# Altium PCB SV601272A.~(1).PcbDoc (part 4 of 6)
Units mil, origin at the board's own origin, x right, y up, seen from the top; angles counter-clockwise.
Board outline 8300 x 9520 mil, 8 copper layers (Top Layer, Signal Layer 1, Signal Layer 2, Signal Layer 3, Signal Layer 4, Signal Layer 5, Signal Layer 6, Bottom Layer), stack 59.2 mil thick; 551 components, 303 nets, 1611 pads, 1923 vias.
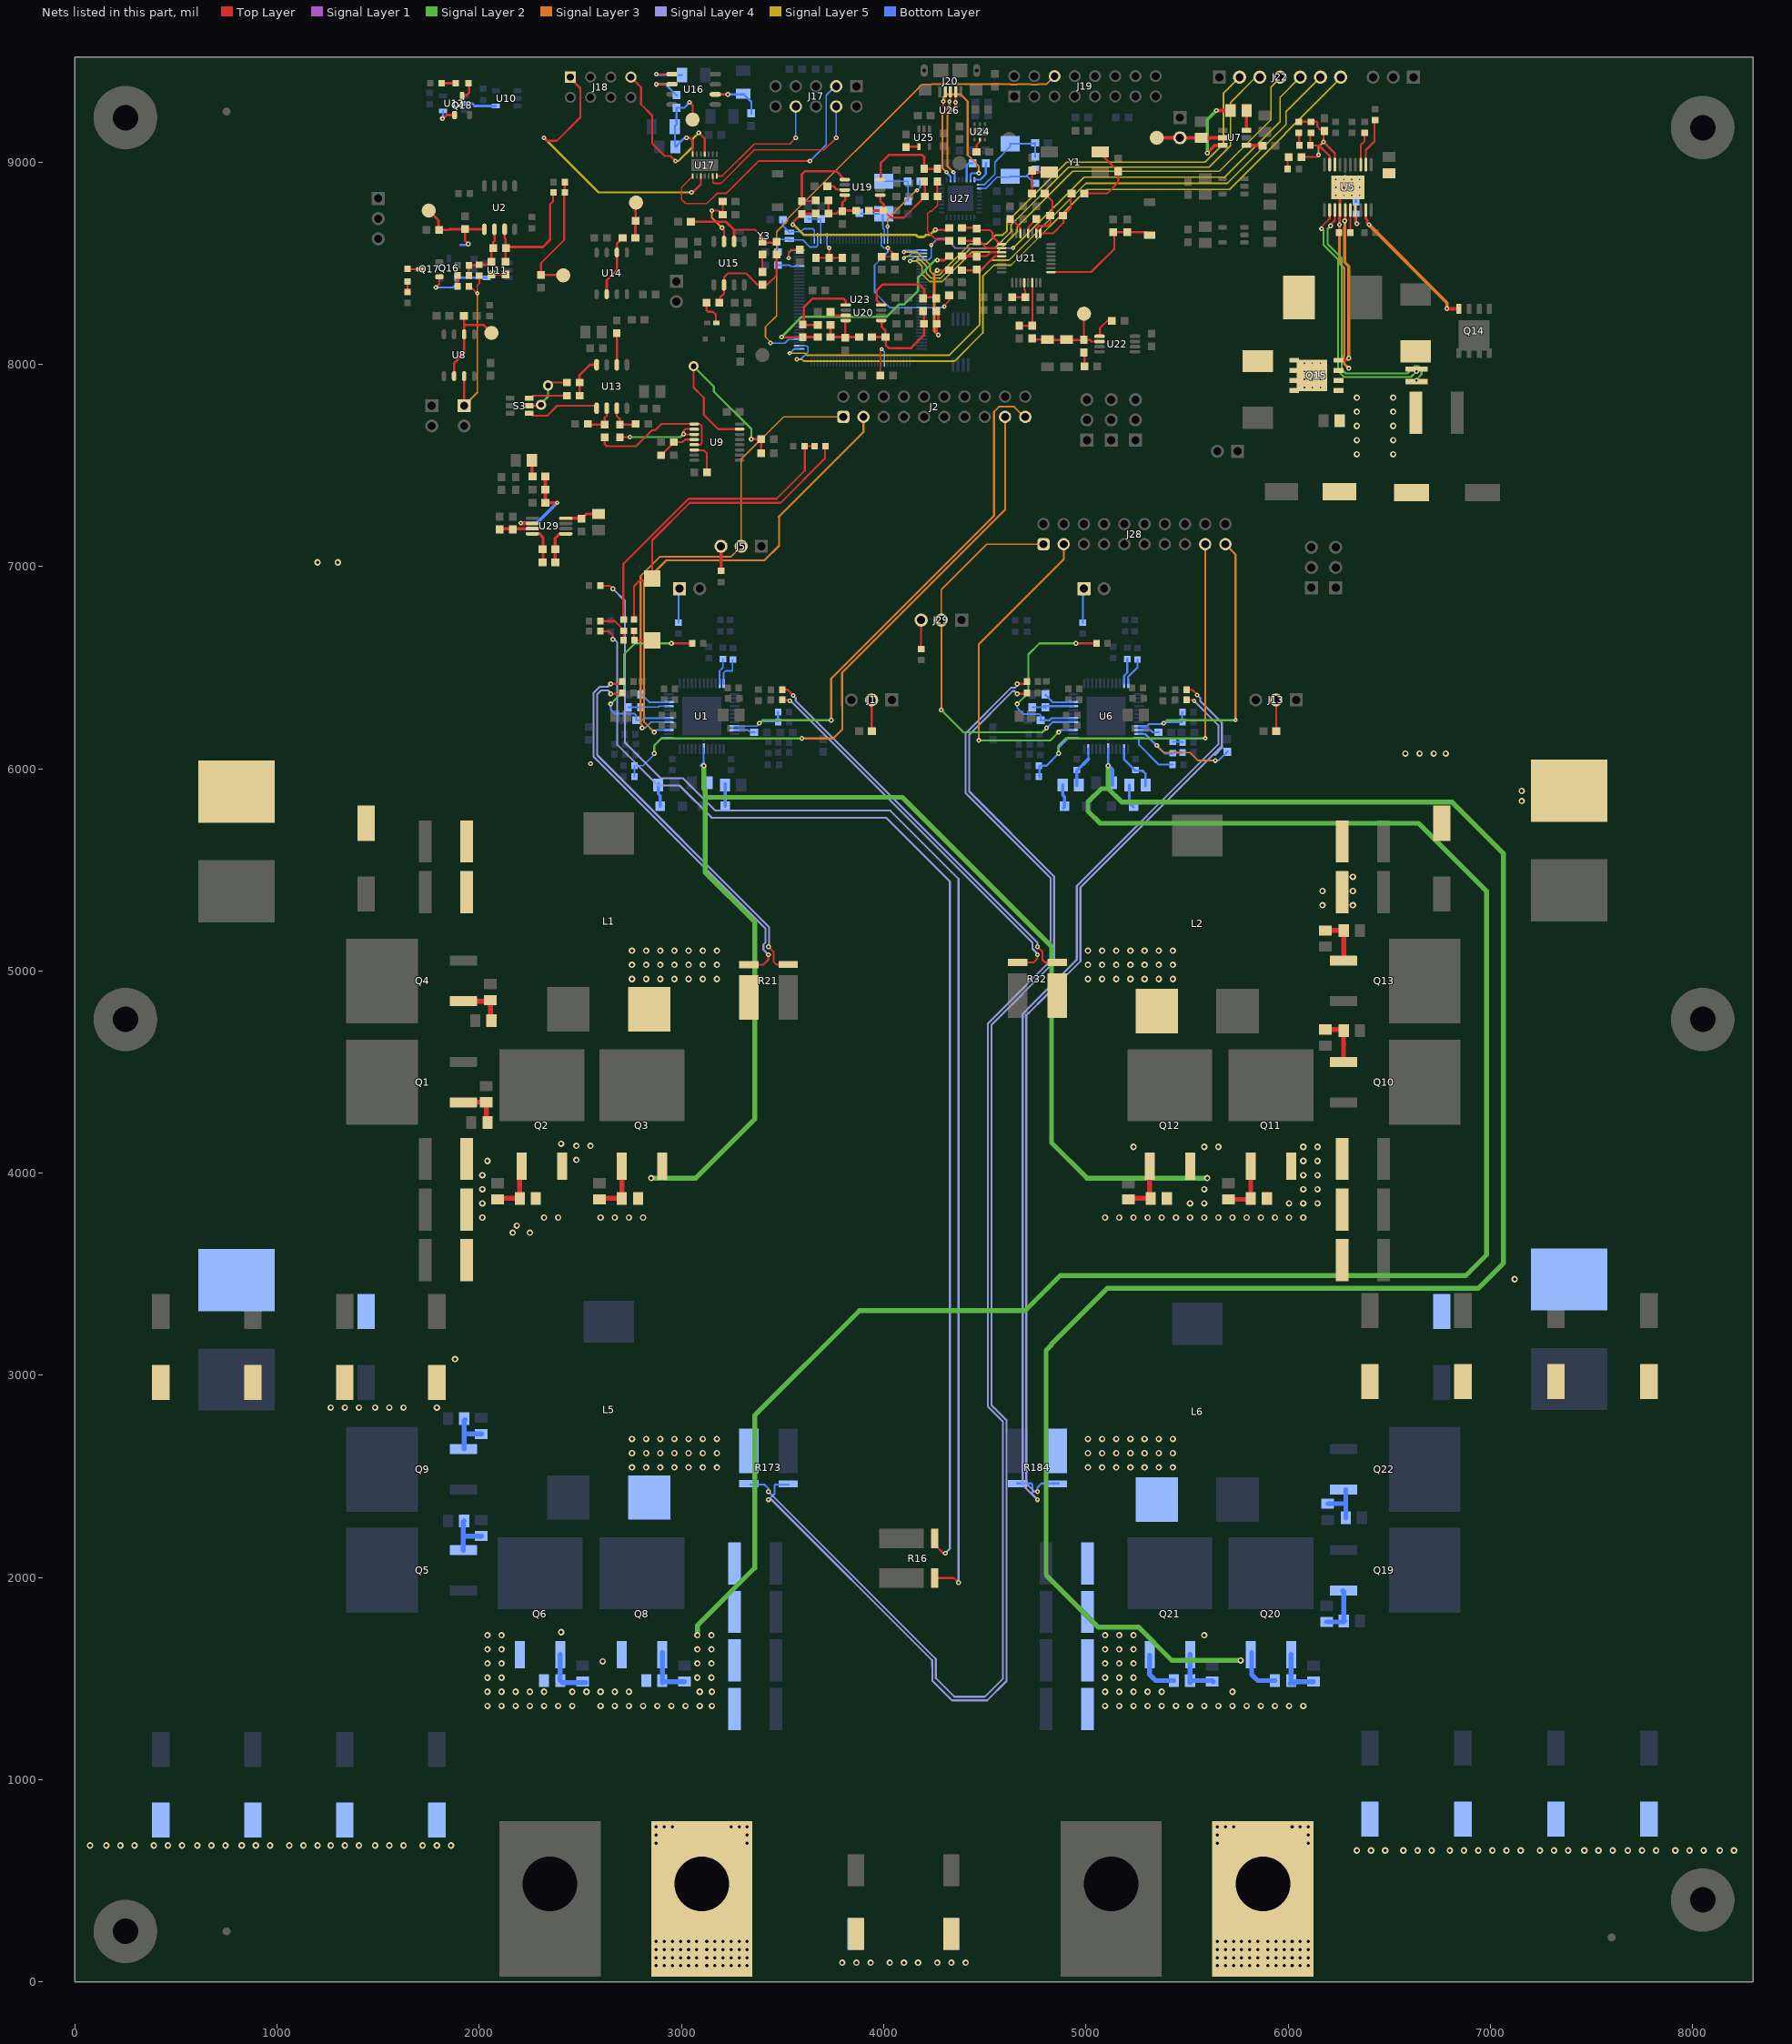
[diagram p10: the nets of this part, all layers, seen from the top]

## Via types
v1: diameter 32, hole 16, Top Layer to Bottom Layer, tented both sides, 622 vias
v2: diameter 24, hole 8, Top Layer to Bottom Layer, 380 vias
v3: diameter 22, hole 8, Top Layer to Bottom Layer, tented both sides, 346 vias
v4: diameter 32, hole 16, Top Layer to Bottom Layer, 237 vias
v5: diameter 24, hole 10, Top Layer to Bottom Layer, tented both sides, 153 vias
v6: diameter 19.68, hole 7.87, Top Layer to Bottom Layer, 70 vias
v7: diameter 24, hole 10, Top Layer to Bottom Layer, 47 vias
v8: diameter 28, hole 8, Top Layer to Bottom Layer, tented top, 24 vias
v9: diameter 22, hole 8, Top Layer to Bottom Layer, 19 vias
v10: diameter 19.68, hole 8, Top Layer to Bottom Layer, 16 vias
v11: diameter 50, hole 28, Top Layer to Bottom Layer, 4 vias
v12: diameter 36, hole 20, Top Layer to Bottom Layer, 2 vias
v13: diameter 26, hole 12, Top Layer to Bottom Layer, 1 vias
v14: diameter 28, hole 12, Top Layer to Bottom Layer, tented both sides, 1 vias
v15: diameter 24, hole 10, Top Layer to Bottom Layer, tented top, 1 vias

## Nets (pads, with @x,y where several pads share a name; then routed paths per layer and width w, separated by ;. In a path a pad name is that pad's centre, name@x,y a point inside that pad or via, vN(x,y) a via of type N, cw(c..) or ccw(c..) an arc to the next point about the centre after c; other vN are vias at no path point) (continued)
NetC46_1: C46.1 C49.1 U5.9 | length 219.5
  Top Layer w10: C49.1@6110.08,9142.2 C46.1@6110.08,9082.2 6152.8,9082.2 6205.43,9029.57 U5.9@6205.43,8987.2
NetC46_2: C46.2 R48.2 | length 63.5
  Top Layer w10: R48.2@6052.52,9144.64 6054.96,9142.2 C46.2@6054.96,9082.2
NetC47_1: C47.1 U5.17 | length 123
  Top Layer w13: U5.17@6333.39,8762.8 6333.39,8696.61 v5@6340,8690
  Bottom Layer w13: v5@6335,8700 C47.1@6335,8744.44 C47.1@6335,8747.44
  other v5: 6340,8695
NetC48_1: C48.1 U5.16 | length 114.2
  Top Layer w10: C48.1@6305,8647.44 C48.1@6307.56,8650 ; C48.1@6307.8,8652.2 U5.16@6307.8,8762.8
NetC49_2: C49.2 R48.1 R49.2 R50.1 U5.8 | length 530.5
  Top Layer w10: R48.1@6050,9200 6140,9200 6145,9195 6145,9175 6166.5,9153.5 R49.2@6178.5,9153.5 ; R50.1@6052.56,9025 6140,9025 v5(6150,9035) ; v5(6175,9100) 6175,9150 R49.2@6178.5,9153.5 ; v5@6175.31,9099.69 6231.02,9043.98 U5.8@6231.02,8987.2 ; R49.2@6180,9153.5 R49.2@6178.5,9153.5 ; R49.2@6180,9155 R49.2@6178.5,9153.5
  Signal Layer 3 w10: v5(6150,9035) 6150,9075 v5(6175,9100)
NetC77_1: C77.1 U7.6 | length 98.4
  Top Layer w16: U7.6@5793.07,9157.4 5793.07,9253.07 C77.1@5795,9255
NetC77_2: C77.2 U7.3 | length 391.1
  Top Layer w16: v7(5600,9045) 5637.6,9082.6 U7.3@5676.93,9082.6 ; v7(5645,9255) C77.2@5715,9255
  Signal Layer 2 w16: v7(5600,9045) 5600,9210 v7(5645,9255)
NetC78_1: C78.1 J16.2 U7.2 V-5.1 | length 330
  Top Layer w16: V-5.1@5350,9120 J16.2@5465,9120 U7.2@5676.93,9120 U7.2@5680,9120
NetC79_1: C79.1 CS2.1 R62.2 | length 1541.6
  Top Layer w10: C79.1@2765,6735 C79.1@2767.56,6737.56 ; C79.1@2765,6740 2765,6902.56 2792.44,6930 2840,6930 CS2.1@2850,6940 ; CS2.1@2855,6940 2855,7129.44 3040.56,7315 3490,7315 3710,7535 R62.2@3710,7597.44
NetC79_2: C79.2 CS1.1 R61.2 | length 137.4
  Top Layer w10: C79.2@2765,6682.44 2765,6635 R61.2@2767.56,6635 CS1.1@2855,6635
NetC85_1: C85.1 R62.1 R64.2 | length 1539.9
  Top Layer w10: C85.1@2710,6735 2712.44,6737.44 2712.44,7012.16 3035.28,7335 3470,7335 3610,7475 R64.2@3610,7595 ; R64.2@3607.56,7595 R64.2@3610,7595 ; R62.1@3660,7595 R62.1@3657.44,7595 R64.2@3610,7595
NetC85_2: C85.2 R61.1 R63.2 | length 185.6
  Top Layer w10: R63.2@2597.56,6730 2670,6730 C85.2@2715,6685 ; R61.1@2710,6635 2715,6640 C85.2@2715,6682.44
NetC87_1: C87.1 R76.2 R78.2 R80.2 R101.2 U2.6 | length 335.8
  Top Layer w12: R78.2@1945,8490 1947.56,8487.44 R101.2@1947.56,8440 ; R78.2@1947.56,8490 1995,8490 R76.2@2000,8495 ; R76.2@2000,8492.56 2042.56,8492.56 R80.2@2060,8510 ; R80.2@2060,8506.5 R80.2@2060,8510 ; C87.1@2068.5,8575 2068.5,8603.5 2075,8610 U2.6@2075,8667.72 ; C87.1@2070,8570 2060,8560 R80.2@2060,8510
NetC87_2: C87.2 C89.2 R81.2 U2.7 | length 634
  Top Layer w10: 2350,8636.69 2350,8790 2365,8805 R81.2@2365,8850
  Top Layer w12: U2.7@2125,8667.72 2125,8625 2130,8620 2130,8580 2315,8580 2350,8615 2350,8636.69 ; C89.2@2130,8506.5 C87.2@2130,8575
NetC89_1: C89.1 R80.1 | length 70.6
  Top Layer w12: R80.1@2060,8443.5 2128.5,8443.5 C89.1@2130,8445
NetC90_1: C90.1 R84.1 U2.5 VREF_LV.1 | length 455.6
  Top Layer w12: VREF_LV.1@1750,8760 1797.56,8712.44 1797.56,8665 R84.1@1801.5,8665 1850,8665 ; 1852.28,8667.72 U2.5@2025,8667.72 ; C90.1@1930,8665 1930,8610 v5(1945,8595)
  Bottom Layer w12: 1907.56,8590 1940,8590 v5(1945,8595)
NetC100_1: C100.1 R65.1 U9.15 | length 1064.5
  Top Layer w10: v11(3060,7990) 3060,7885 3110,7835 3110,7750 3181.02,7678.98 U9.15@3287.2,7678.98 ; v5(3345,7630) R65.1@3393.5,7630 ; C100.1@3393.5,7560 3393.5,7628.5 R65.1@3395,7630
  Signal Layer 2 w10: v11(3060,7990) 3160,7890 3160,7865 3345,7680 v5(3345,7630)
NetC102_1: C102.1 J35.1 R76.1 U8.3 | length 872.2
  Top Layer w8: C102.1@1945,8385 C102.1@1947.56,8385 1955,8385 v3(1990,8350) 1990,8390 2000,8400 R76.1@2000,8435
  Top Layer w10: J35.1@1925,7800 U8.3@1925,7941.65
  Signal Layer 3 w8: 1990,7860 v3(1990,8350)
  Signal Layer 3 w10: J35.1@1925,7795 1990,7860
NetC102_2: C102.2 R101.1 | length 52.4
  Top Layer w12: C102.2@1892.44,8385 R101.1@1892.44,8437.44
NetC104_1: C104.1 R68.1 U13.2 | length 174.1
  Top Layer w10: C104.1@2535,7705 2538.5,7701.5 R68.1@2620,7701.5 2620,7735 2630,7745 U13.2@2630,7782.72 U13.2@2630,7785
NetC105_1: C105.1 R69.1 U13.3 | length 171.2
  Top Layer w10: U13.3@2680,7785 U13.3@2680,7782.72 2680,7745 2695,7730 R69.1@2695,7701.5 2771.5,7701.5 C105.1@2775,7705
NetC114_1: C114.1 R74.2 R82.1 U15.2 | length 546.6
  Top Layer w10: 3260,8665 3365,8665 3400,8630 R82.1@3400,8610 ; R82.1@3400,8606.5 R82.1@3400,8610 ; C114.1@3480,8601.5 3408.5,8601.5 R82.1@3400,8610
  Top Layer w12: R74.2@3046.5,8705 3220,8705 3260,8665 U15.2@3260,8610
NetC114_2: C114.2 C115.1 R162.1 U15.6 | length 546.3
  Top Layer w10: R162.1@3190,8301.5 3190,8330 3210,8350 U15.6@3210,8392.72 3210,8430 3230,8450 3320,8450 3375,8395 C115.1@3400,8395 ; C115.1@3400,8393.5 3423.5,8393.5 3470,8440 3470,8525 C114.2@3480,8535
NetC115_2: C115.2 R82.2 | length 88.5
  Top Layer w10: C115.2@3400,8456.5 R82.2@3400,8543.5 R82.2@3400,8545
NetC118_2: C118.2 R93.2 U15.3 | length 304.4
  Top Layer w10: v5(3150,8760) 3185,8760 R93.2@3203.5,8741.5 ; v7@3200,8670 3210,8660 U15.3@3210,8607.28 ; C118.2@3203.5,8805 R93.2@3203.5,8741.5 ; R93.2@3205,8740 R93.2@3203.5,8741.5
  Signal Layer 3 w10: v5@3150,8765 v5(3150,8760) 3150,8725 v7(3200,8675)
NetC122_1: C122.1 L4.2 U16.2 | length 252.2
  Top Layer w10: U16.2@3167.28,9335 v7(3230,9335)
  Bottom Layer w10: v7(3230,9335) C122.1@3305,9335 ; C122.1@3305,9337.91 3345,9297.91 L4.2@3345,9241.5 L4.2@3345,9240
NetC123_1: C123.1 U16.5 | length 207.7
  Top Layer w10: v5(2875,9435) U16.5@2952.72,9435
  Bottom Layer w10: v5(2875,9435) 2880,9430 C123.1@3002.91,9430
NetC124_1: C124.1 C125.1 R96.2 U17.7 VREF_DAC.1 | length 543
  Top Layer w10: v5(3025,9120) 3040,9120 3055,9105 U17.7@3055,9040 ; v3(3040,9295) 3055,9280 VREF_DAC.1@3055,9210
  Bottom Layer w10: C125.1@2965,9175 2975,9185 R96.2@2975,9268.5 3013.5,9268.5 v3(3040,9295) ; C125.1@2967.09,9175 2967.09,9082.91 C124.1@2972.5,9077.5 ; C124.1@2970,9075 C124.1@2972.5,9077.5 ; C124.1@2975,9075 C124.1@2972.5,9077.5 ; v5(3025,9120) 3015,9120 C124.1@2972.5,9077.5
NetC142_1: C142.1 C143.1 R111.1 R112.2 U19.1 | length 494.7
  Top Layer w10: R112.2@4000,8760 4035,8725 4100,8725 4200,8825 R111.1@4200,8830
  Top Layer w12: C143.1@3926.5,8760 R112.2@3998.5,8760 4000,8760 4000,8790 3982.6,8807.4 U19.1@3982.6,8836.61 ; C142.1@4200,8905 4203.5,8901.5 R111.1@4203.5,8830
NetC142_2: C142.2 R113.1 U19.4 | length 439.8
  Top Layer w12: U19.4@3985,8915 3985,8995 4025,9035 4190,9035 4200,9025 C142.2@4200,8966.5 4263.5,8966.5 R113.1@4265,8965
NetC143_2: C143.2 C144.1 R114.2 R117.1 U19.8 | length 292.1
  Top Layer w12: C144.1@3725,8810 3726.5,8808.5 R117.1@3726.5,8745 3765,8745 3776.5,8756.5 R114.2@3795,8756.5 R114.2@3795,8760 ; U19.8@3810,8835 3810,8815 3795,8800 R114.2@3795,8760 ; C143.2@3863.5,8760 R114.2@3795,8760
NetC144_2: C144.2 R115.1 U19.5 | length 437.3
  Top Layer w12: R115.1@3595,8806.5 3661.5,8806.5 C144.2@3665,8810 ; R115.1@3595,8810 3595,8940 3610,8955 3765.79,8955 U19.5@3807.4,8913.39
NetC145_2: C145.2 C146.2 U21.12 | length 141.2
  Top Layer w10: C145.2@4635,8331.5 4698.5,8331.5 C146.2@4700,8330 ; U21.12@4695,8405 4695,8370 4700,8365 C146.2@4700,8331.5
NetC147_1: C147.1 R118.2 U21.1 | length 238.4
  Top Layer w10: C147.1@4460,8670 4466.13,8663.87 4524.89,8663.87 4538.87,8649.89 4538.87,8630.11 ; 4540,8635 4540,8630 4576.1,8593.9 U21.1@4582.95,8593.9
  Top Layer w12: R118.2@4386.5,8675 C147.1@4455,8675
NetC147_2: C147.2 R119.2 U21.2 | length 212.4
  Top Layer w10: C147.2@4476.5,8608.5 4510,8575 U21.2@4585,8575
  Top Layer w12: R119.2@4386.5,8610 C147.2@4460,8610 ; C147.2@4460,8608.5 C147.2@4476.5,8608.5
NetC148_1: C148.1 R125.2 U21.3 | length 206.6
  Top Layer w10: C148.1@4460,8535 4510,8535 4529.53,8554.53 U21.3@4582.95,8554.53
  Top Layer w12: R125.2@4386.5,8535 4455,8535 C148.1@4460,8530
NetC148_2: C148.2 R127.2 U21.4 | length 232.5
  Top Layer w10: C148.2@4460,8465 4480,8465 4550,8535 U21.4@4580.91,8535 ; U21.4@4580.91,8534.84 U21.4@4582.95,8534.84 ; U21.4@4582.95,8535 U21.4@4590,8535
  Top Layer w12: R127.2@4386.5,8465 C148.2@4460,8465
NetC149_2: C149.2 R121.1 S1.1 U21.17 | length 632.2
  Top Layer w10: U21.17@4827.05,8456.1 5026.1,8456.1 5140,8570 R121.1@5140,8650 ; R121.1@5135,8653.5 5201.5,8653.5 C149.2@5205,8650 ; C149.2@5200,8653.5 C149.2@5205,8653.5 5301.5,8653.5 S1.1@5315,8640
NetC150_1: C150.1 C151.1 R124.1 R126.2 U20.1 | length 544.3
  Top Layer w12: C151.1@3940,8135 C151.1@3941.5,8135 R126.2@4008.5,8135 4008.5,8166.5 3990,8185 U20.1@3990,8215 ; R126.2@4010,8135 4010,8095 4025,8080 4135,8080 4198.5,8143.5 R124.1@4198.5,8200 4198.5,8268.5 C150.1@4200,8270
NetC150_2: C150.2 R128.1 U20.4 | length 448.7
  Top Layer w10: 3995,8395 4175,8395
  Top Layer w12: U20.4@3987.6,8293.39 3965,8315.98 3965,8365 3995,8395 ; 4175,8395 4200,8370 4200,8331.5 4266.5,8331.5 R128.1@4270,8335
NetC151_2: C151.2 C154.1 R129.2 R132.1 U20.8 | length 297.7
  Top Layer w12: C154.1@3735,8200 3736.5,8198.5 C154.1@3736.5,8195 R132.1@3736.5,8135 R129.2@3810,8135 ; R129.2@3810,8131.5 R129.2@3810,8135 ; U20.8@3815,8219.47 3810,8214.47 R129.2@3810,8135 ; C151.2@3878.5,8135 R129.2@3810,8135
NetC152_1: C152.1 R135.2 Y1.1 | length 388
  Top Layer w10: R135.2@4991.5,8856.5 R135.2@4991.5,8845 5105,8845 5160,8900 C152.1@5160,8953.5 5075,9038.5 Y1.1@5075,9050
NetC153_1: C153.1 R136.1 Y1.3 | length 201.7
  Top Layer w10: R136.1@4733.5,8845 4733.5,8958.5 C153.1@4735,8960 ; C153.1@4735,8955 4740,8950 Y1.3@4819.02,8950
NetC154_2: C154.2 R130.1 U20.5 | length 403.9
  Top Layer w12: C154.2@3673.5,8195 3605,8195 3605,8280 3650,8325 3800,8325 3812.4,8312.6 U20.5@3812.4,8293.39
NetC155_1: C155.1 R133.2 U21.14 | length 280
  Top Layer w10: C155.1@4670,8195 4673.5,8191.5 R133.2@4735,8191.5 U21.14@4735,8405
NetC156_1: C156.1 U21.28 | length 90.1
  Top Layer w10: U21.28@4715,8645 4715,8678.5 C156.1@4755,8718.5
NetC157_1: C157.1 U22.5 | length 118
  Top Layer w10: U22.5@5070,8135 5070,8180 5105,8215 C157.1@5128.5,8215
NetC158_1: C158.1 C159.1 R133.1 R134.2 U22.6 VREF_ADC.1 | length 430.2
  Top Layer w10: R133.1@4735,8125 4738.07,8121.93 C159.1@4810,8121.93 ; C159.1@4810,8120 5020,8120 5027.2,8112.8 U22.6@5067.4,8112.8 ; R134.2@4990,8121.5 4990,8215
NetC161_1: C161.1 R134.1 | length 71.5
  Top Layer w10: R134.1@4990,8060 4993.5,8056.5 C161.1@4993.5,7990
NetC162_1: C162.1 U23.88 Y2.2 | length 241.9
  Bottom Layer w6: 3995,8690 3997.13,8687.87 3997.13,8671.94 4003.11,8665.96 U23.88@4003.11,8623.15
  Bottom Layer w8: C162.1@3880,8750 3885.71,8744.29 3995,8744.29 3995,8690
NetC163_2: C163.2 R146.2 U23.68 | length 161.7
  Bottom Layer w6: U23.68@3688.15,8623.15 3688.15,8718.15 3688.5,8718.5 R146.2@3690,8720
  Bottom Layer w8: C163.2@3625,8720 3626.5,8718.5 R146.2@3688.5,8718.5
NetC164_1: C164.1 R145.1 Y2.1 | length 217
  Bottom Layer w8: Y2.1@4000,8905 R145.1@4118.5,8905 ; C164.1@4120,8806.5 R145.1@4120,8905
NetC169_2: C169.2 R139.1 R141.2 U23.70 | length 237.9
  Top Layer w8: C169.2@3665,8526.5 R141.2@3795,8526.5 3803.5,8536.5 R141.2@3805,8535 ; R139.1@3730,8536.5 v3(3730,8575)
  Bottom Layer w6: U23.70@3720,8625 3720,8585 v3(3730,8575)
NetC170_2: C170.2 U23.67 Y3.1 | length 311
  Bottom Layer w6: 3665,8580 3672.4,8587.4 U23.67@3672.4,8623.15
  Bottom Layer w8: C170.2@3475,8555 3475,8610 3482.28,8617.28 Y3.1@3534.02,8617.28 Y3.1@3534.02,8614.02 ; Y3.1@3535,8615 3600,8615 3635,8580 3665,8580
NetC171_2: C171.2 U23.66 Y3.4 | length 237.2
  Bottom Layer w6: 3650,8670 3656.65,8663.35 U23.66@3656.65,8623.15
  Bottom Layer w8: C171.2@3500,8710 3500,8686.73 Y3.4@3534.02,8652.72 ; Y3.4@3540,8655 3590,8655 3605,8670 3650,8670
NetC172_1: C172.1 C173.1 C174.2 U23.87 U23.115 | length 904.8
  Top Layer w8: C172.1@3990,8545 C172.1@3990,8531.5 4053.5,8531.5 C173.1@4055,8530 ; v3(4020,8575) 4055,8540 C173.1@4055,8531.5 ; v3(4300,8285) 4300,8290 4323.5,8313.5 C174.2@4323.5,8340
  Bottom Layer w6: U23.87@3987.36,8623.15 3987.36,8587.64 4000,8575 v3(4020,8575) ; 4020,8290 4029.37,8280.63 U23.115@4188.15,8280.63 4295.63,8280.63 v3(4300,8285)
  Bottom Layer w8: 4020,8290 3955,8355 3955,8490 4020,8555 v3(4020,8575) ; v3@4295,8285 v3(4300,8285)
NetC181_1: C181.1 U24.2 | length 67.8
  Top Layer w10: C181.1@4460,9050 4460,9085 4475,9100 U24.2@4475,9111.61
NetC184_1: C184.1 U25.4 | length 64.7
  Top Layer w10: C184.1@4110,9075 4110.71,9075.71 U25.4@4174.41,9075.71
NetC185_2: C185.2 R150.2 U27.26 Y4.2 | length 382.2
  Bottom Layer w8: U27.26@4473.31,8869.21 4504.21,8869.21 4560,8925 Y4.2@4625,8925 ; Y4.2@4625,8929.29 4709.21,8929.29 ; 4700,8930 4703.5,8930 4709.21,8929.29 ; C185.2@4743.5,8895 4709.21,8929.29 ; R150.2@4750,8965 4740,8965 4704.29,8929.29 4709.21,8929.29
NetC186_2: C186.2 R150.1 U27.25 Y4.1 | length 471.3
  Bottom Layer w8: U27.25@4473.31,8888.9 4498.9,8888.9 4550,8940 4550,9000 4625,9075 Y4.1@4625,9090 ; Y4.1@4625,9090.71 4740.71,9090.71 C186.2@4745,9095 ; C186.2@4748.5,9095 4748.5,9026.5 R150.1@4750,9025
NetC192_2: C192.2 R95.1 U6.23 | length 206.9
  Bottom Layer w9.8: U6.23@5011.42,6097.6 5011.42,6071.43 5012.51,6070.34 5012.51,6047.51
  Bottom Layer w16: R95.1@4955,5915 4955,5990 5012.51,6047.51
NetC195_1: C195.1 R166.1 U6.14 | length 250.1
  Bottom Layer w9.8: 5188.58,6046.42 U6.14@5188.58,6097.6
  Bottom Layer w12: 5188.58,6046.42 5240,5995 5240,5990 5280,5990 5285,5985 5295,5975 R166.1@5295,5915
NetC197_1: C197.1 U6.12 | length 242.2
  Bottom Layer w10: U6.12@5262.4,6151.73 5262.4,6117.6 5360,6020 C197.1@5430,6020
NetC201_1: C201.1 C204.1 R168.1 U6.11 | length 656.8
  Signal Layer 3 w8: v5(5350,6115) 5385,6080 5515,6080 5555,6040 v5(5640,6040)
  Bottom Layer w10: U6.11@5262.4,6171.42 5293.58,6171.42 v5(5350,6115) 5390,6075 5430,6075 5435,6080 C204.1@5477.44,6080 ; v5(5640,6040) 5655,6040 R168.1@5700,6085
NetC201_2: C201.2 R172.2 | length 51.1
  Bottom Layer w10: C201.2@5430,6132.56 5477.44,6132.56 R172.2@5480,6130
NetC218_1: C218.1 R195.1 U9.4 | length 189.4
  Top Layer w10: C218.1@2898.5,7550 2958.5,7610 R195.1@2960,7610 ; R195.1@2965,7615 3005,7615 3017.8,7627.8 U9.4@3062.8,7627.8
NetC221_1: C221.1 C222.1 U29.1 | length 186.6
  Top Layer w15: C222.1@2375,7015 2375,7140 2396.61,7161.61 U29.1@2427.68,7161.61
NetC221_2: C221.2 C222.2 U29.8 | length 189.6
  Top Layer w15: U29.8@2262.32,7161.61 2298.39,7161.61 2315,7145 C222.2@2315,7015
NetC223_1: C223.1 L7.1 U29.4 | length 186.3
  Top Layer w15: U29.4@2427.68,7238.39 2508.39,7238.39 2530,7260 L7.1@2605,7260
NetC224_1: C224.1 C225.1 U29.7 | length 158.5
  Top Layer w15: C225.1@2105,7190 2107.8,7187.2 U29.7@2262.32,7187.2
NetC226_1: C226.1 C227.1 R201.1 U29.6 | length 459.6
  Top Layer w17: v3@2210,7215 2212.2,7212.8 U29.6@2262.32,7212.8 ; R201.1@2330,7445 2326.5,7441.5 C227.1@2326.5,7380 C226.1@2326.5,7315 v3@2380,7315
  Bottom Layer w17: v3(2205,7215) 2285,7215 v3(2385,7315)
NetCV_1: CV.1 R81.1 R86.1 R163.1 | length 618.3
  Top Layer w10: R163.1@2305,8441.5 2413.5,8441.5 CV.1@2415,8440 ; R163.1@2305,8445 2305,8500 2420,8615 R81.1@2420,8850 ; R81.1@2422.56,8850 R86.1@2422.56,8905
NetD1_1: D1.1 R54.2 | length 114.1
  Bottom Layer w16: R54.2@2885,5925 2885,5875 2894.88,5865.12 D1.1@2894.88,5815
NetD2_1: D2.1 R55.2 | length 109.9
  Bottom Layer w16: D2.1@3215.12,5815 R55.2@3215.12,5924.88
NetD3_1: D3.1 R162.2 | length 133.9
  Top Layer w10: R162.2@3123.5,8305 3123.5,8266.5 3130,8260 3155,8260 3170,8245 D3.1@3170,8205
NetD4_1: D4.1 R95.2 | length 121.2
  Bottom Layer w16: R95.2@4885,5920 4885,5870 4895,5860 4895,5810 D4.1@4890,5805
NetD6_2: D6.2 L3.2 Q15.5 Q15.6 Q15.7 Q15.8 Q15.9
  other v8: 6080,7885 6120,7885 6160,7885 6080,7925 6120,7925 6160,7925 6080,7965 6120,7965 6160,7965 6080,8005 6120,8005 6160,8005
NetD7_2: D7.2 R47.2 U5.12 | length 1257.4
  Top Layer w10: v5(6165.53,8670) 6165.53,8680.53 6205.43,8720.43 U5.12@6205.43,8762.8
  Signal Layer 2 w10: v5(6165.53,8670) 6175,8660.53 6175,8590 6247.13,8517.87 6247.13,7967.87 6277.87,7937.13 6607.13,7937.13 v7(6635,7965)
NetD10_1: D10.1 R166.2 | length 118.3
  Bottom Layer w12: R166.2@5215,5920 5215,5830 D10.1@5235,5810
NetD11_1: D11.1 Q17.3 | length 64.8
  Top Layer w10: D11.1@1645,8470 1702.76,8470 Q17.3@1707.76,8465
NetD11_2: D11.2 R90.2 | length 52.4
  Top Layer w10: R90.2@1645,8357.56 D11.2@1645,8408.5 D11.2@1645,8410
NetD12_1: D12.1 Q18.3 | length 92.4
  Top Layer w12: Q18.3@1915,9327.24 1917.76,9330 1935,9330 1950,9345 D12.1@1950,9395
NetD12_2: D12.2 R91.2 | length 68.5
  Top Layer w12: R91.2@1815,9390 D12.2@1883.5,9390
NetIBAT_1: IBAT.1 R72.2 R73.2 | length 181.2
  Top Layer w12: R72.2@2771.5,8625 2771.5,8708.5 2770,8710 R73.2@2773.5,8713.5 ; R73.2@2773.5,8710 R73.2@2773.5,8713.5 ; IBAT.1@2775,8800 2773.5,8798.5 R73.2@2773.5,8713.5
NetJ1_2: J1.2 R4.2 | length 152.6
  Top Layer w9.8: R4.2@3940,6187.44 J1.2@3940,6340
NetJ3_1: J3.1 R7.1 | length 167.4
  Bottom Layer w10: R7.1@2985,6722.56 J3.1@2985,6890
NetJ5_3: J5.3 R12.1 | length 130
  Top Layer w16: R12.1@3195,6975 J5.3@3195,7105
NetJ13_2: J13.2 R34.2 | length 155.6
  Top Layer w10: J13.2@5940,6340 5941.5,6338.5 R34.2@5941.5,6185
NetJ18_1: J18.1 U17.10 | length 1398.1
  Top Layer w10: v7(2320,9120) 2335,9105 2383.5,9105 2500,9221.5 2500,9365 J18.1@2450,9415 ; v7(3050,8850) 3055,8850 3095.31,8890.32 U17.10@3095.31,8930.87
  Signal Layer 5 w10: v7(2320,9120) 2590,8850 v7(3050,8850) v7@3055,8850
NetJ18_7: J18.7 U17.4 | length 837.5
  Top Layer w10: J18.7@2750,9420 2800,9370 2800,9285 2855,9230 2855,9091.5 2916.5,9030 2945,9030 v7(2970,9005) ; v5(3085,9145) 3115,9115 U17.4@3115,9039.13
  Signal Layer 5 w10: v7(2970,9005) 2985,9005 3055,9075 3055,9115 v5(3085,9145)
NetJ20_2: J20.2 U26.1 U27.19 | length 503.5
  Top Layer w8: U26.1@4345,9265 4355,9275 v3(4355,9295) 4355.59,9295.59 J20.2@4355.59,9347.6
  Signal Layer 3 w10: v3(4345,8950) 4315,8980 4315,9235 4355,9275 v3(4355,9295)
  Bottom Layer w10: v3@4342.5,8952.5 v3(4345,8950) 4350.47,8944.53 U27.19@4350.47,8913.31
NetJ20_3: J20.3 U26.2 U27.18 | length 495.7
  Top Layer w8: U26.2@4325,9265 v3(4325,9300) 4330,9305 J20.3@4330,9347.6
  Signal Layer 3 w10: v3(4310,8950) 4290,8970 4290,9240 4325,9275 v3(4325,9300)
  Bottom Layer w10: v3@4315,8945 4330.79,8929.21 U27.18@4330.79,8913.31
NetJ20_4: J20.4 U26.3 U27.23 | length 698.2
  Top Layer w8: J20.4@4304.41,9347.6 4302.13,9345.32 4302.13,9307.13 v3(4295,9300) 4295,9275 U26.3@4305,9265
  Signal Layer 3 w10: v3(4295,9300) 4295,9320 4310,9335 4380,9335 4415,9300 4415,9035 4470,8980 v5(4470,8945)
  Bottom Layer w10: U27.23@4429.21,8913.31 4429.21,8939.21 4435,8945 v5(4470,8945)
NetJ22_2: J22.2 U23.97 | length 2398.5
  Signal Layer 5 w6: 4242.5,8447.5 4247.87,8442.13 4274.47,8442.13 4305,8472.65 4305,8475
  Signal Layer 5 w8: v3(4100,8555) 4165,8555 4230,8490 4230,8460 4242.5,8447.5 ; 4305,8472.65 4416.17,8583.83 ; 4415,8585 4425,8595 4510,8595 4554.07,8639.07 ; 4555,8640 4554.07,8639.07 ; J22.2@5760,9420 5680,9340 5680,9090 5590,9000 4905,9000 4610,8705 4610,8660 4589.07,8639.07 4554.07,8639.07
  Bottom Layer w6: v3(4100,8555) 4109.09,8564.09 U23.97@4188.15,8564.09
NetJ22_3: J22.3 U23.98 | length 2487.2
  Signal Layer 5 w6: v3(4100,8525) 4105,8525 4115,8535 4161.03,8535 4210,8486.03 4210,8450 4235,8425 4275,8425
  Signal Layer 5 w8: 4275,8425 4280,8425 4430,8575 4550,8575 4630,8655 4630,8690 4915,8975 5610,8975 5715,9080 5715,9295 5840,9420 J22.3@5860,9420
  Bottom Layer w6: v3(4100,8525) 4108.13,8533.13 4121.87,8533.13 4137.09,8548.35 U23.98@4188.15,8548.35
NetJ22_4: J22.4 U23.99 | length 2486.3
  Signal Layer 5 w8: v3(4130,8510) 4165,8510 4190,8485 4190,8445 4225.87,8409.13 4289.13,8409.13 4435,8555 4560,8555 4662.5,8657.5 ; 4660,8660 4660,8680 4935,8955 5660,8955 5915,9210 5915,9370 J22.4@5960,9415
  Bottom Layer w6: v3(4130,8510) 4152.6,8532.6 U23.99@4188.15,8532.6
NetJ22_5: J22.5 U23.100 | length 2388.7
  Signal Layer 1 w8: v3(4235,8590) 4265,8620 4310,8620 4355,8575 v3(4640,8575)
  Signal Layer 5 w8: v3(4640,8575) 4990,8925 5685,8925 5960,9200 5960,9320 J22.5@6060,9420
  Bottom Layer w6: U23.100@4188.15,8516.85 4221.85,8516.85 4235,8530
  Bottom Layer w8: 4235,8530 v3(4235,8590)
NetJ22_6: J22.6 U23.33 | length 3447.5
  Signal Layer 5 w8: v3(3535,8055) 3610,8055 3620,8045 4325,8045 4474.13,8194.13 4474.13,8441.58 4475,8442.45 4475,8460 4530,8515 4620,8515 5000,8895 5700,8895 5990,9185 5990,9250 J22.6@6160,9420
  Bottom Layer w6: v3(3535,8055) 3555.91,8075.91 U23.33@3581.85,8075.91
NetJ22_7: J22.7 U23.34 | length 3583.5
  Signal Layer 5 w8: v3(3570,8025) 3595,8025 3605,8015 4350,8015 4490,8155 4490,8435 4545,8490 4630,8490 5005,8865 5710,8865 6260,9415 J22.7@6260,9420
  Bottom Layer w6: U23.34@3581.85,8091.65 3618.35,8091.65 3625,8085 3625,8060
  Bottom Layer w8: v3(3570,8025) 3590,8025 3625,8060
NetJ27_1: J27.1 R89.1 | length 178.7
  Bottom Layer w10: R89.1@4985,6722.56 4985,6880 J27.1@5000,6895
NetJ29_3: J29.3 R157.1 | length 142.4
  Top Layer w10: R157.1@4185,6592.56 J29.3@4185,6735
NetL1_2: L1.2 R21.1
  other v1: 2755,4960 2825,4960 2895,4960 2965,4960 3035,4960 3105,4960 3175,4960 2755,5030 2825,5030 2895,5030 2965,5030 3035,5030 3105,5030 3175,5030 2755,5100 2825,5100 2895,5100 2965,5100 3035,5100 3105,5100 3175,5100
NetL2_1: L2.1 R32.2
  other v1: 5010,4960 5080,4960 5150,4960 5220,4960 5290,4960 5360,4960 5430,4960 5010,5030 5080,5030 5150,5030 5220,5030 5290,5030 5360,5030 5430,5030 5010,5100 5080,5100 5150,5100 5220,5100 5290,5100 5360,5100 5430,5100
NetL5_1: L5.1 R173.1
  other v1: 2755,2545 2825,2545 2895,2545 2965,2545 3035,2545 3105,2545 3175,2545 2755,2615 2825,2615 2895,2615 2965,2615 3035,2615 3105,2615 3175,2615 2755,2685 2825,2685 2895,2685 2965,2685 3035,2685 3105,2685 3175,2685
NetL6_2: L6.2 R184.2
  other v1: 5010,2545 5080,2545 5150,2545 5220,2545 5290,2545 5360,2545 5430,2545 5010,2615 5080,2615 5150,2615 5220,2615 5290,2615 5360,2615 5430,2615 5010,2685 5080,2685 5150,2685 5220,2685 5290,2685 5360,2685 5430,2685
NetL8_2: L8.2 R201.2 | length 81.5
  Top Layer w17: L8.2@2260,7525 2260,7448.5 R201.2@2263.5,7445
NetQ1_1: Q1.1 R22.2 R26.2 | length 232.2
  Top Layer w24: Q1.1@1915,4344.67 1920.33,4350 R22.2@2040,4350 ; R26.2@2035,4245 R22.2@2035,4350
NetQ2_1: Q2.1 R24.1 R27.2 | length 278.9
  Top Layer w24: R27.2@2080,3875 R24.1@2200,3875 2200,3945 Q2.1@2200,4033.94
NetQ3_1: Q3.1 R25.1 R28.2 | length 283.1
  Top Layer w24: R28.2@2590,3865 2600,3875 R25.1@2705,3875 2705,3945 Q3.1@2705,4033.94 Q3.1@2705,4038.94
NetQ4_1: Q4.1 R29.2 R30.2 | length 256.7
  Top Layer w24: Q4.1@1920.33,4850 R29.2@2055,4850 ; R30.2@2055,4740 R29.2@2055,4850 ; R29.2@2055,4855 R29.2@2055,4850 ; R29.2@2060,4845 R29.2@2055,4850
NetQ5_1: Q5.1 R174.2 R179.2 | length 238.7
  Bottom Layer w24: 1920,2200 1921.06,2201.06 ; Q5.1@1921.06,2135 1921.06,2201.06 ; R179.2@1925,2280 1921.06,2276.06 1921.06,2201.06 ; R174.2@2010,2205 1925,2205 1921.06,2201.06
NetQ6_1: Q6.1 R175.1 R180.2 | length 258.1
  Bottom Layer w24: Q6.1@2400,1618.94 R175.1@2400,1490 2410,1480 R180.2@2525,1480
NetQ8_1: Q8.1 R176.1 R181.2 | length 262.1
  Bottom Layer w24: Q8.1@2905,1630 Q8.1@2905,1618.94 2905,1480 2910,1485 R181.2@3015,1485
NetQ9_1: Q9.1 R182.2 R183.2 | length 232.1
  Bottom Layer w24: Q9.1@1925,2635 1925,2710 ; R183.2@1930,2780 1925,2775 1925,2710 ; R182.2@2010,2710 1925,2710
NetQ10_1: Q10.1 R33.1 R37.2 | length 255.2
  Top Layer w24: R33.1@6180,4705 R33.1@6185,4710 6270,4710 6273.94,4706.06 6273.94,4633.94 ; Q10.1@6273.94,4550 6273.94,4633.94 ; 6275,4635 6273.94,4633.94
NetQ11_1: Q11.1 R35.1 R38.2 | length 276
  Top Layer w24: R38.2@5705,3870 5810,3870 R35.1@5815,3865 ; R35.1@5815,3875 Q11.1@5815,4033.94 Q11.1@5815,4038.94
NetQ12_1: Q12.1 R36.1 R39.2 | length 281
  Top Layer w24: R39.2@5205,3870 5210,3875 R36.1@5315,3875 ; R36.1@5315,3870 R36.1@5315,3875 ; Q12.1@5315,4033.94 5315,3945 R36.1@5315,3875 ; R36.1@5320,3875 R36.1@5315,3875
NetQ13_1: Q13.1 R40.1 R41.2 | length 245
  Top Layer w24: R40.1@6185,5200 R41.2@6275,5200 ; Q13.1@6275,5050 R41.2@6275,5200 ; R41.2@6280,5200 R41.2@6275,5200
NetQ14_4: Q14.4 U5.19 | length 718.2
  Top Layer w13: U5.19@6384.57,8762.8 6384.57,8719.95 6390.87,8713.65 6390.87,8699.13 v5(6400,8690) v5@6400,8694.76
  Top Layer w16: v7(6785,8275) 6785.7,8274.3 Q14.4@6844.51,8274.3
  Signal Layer 3 w16: v5(6400,8690) 6785,8305 v7(6785,8275)
NetQ15_4: Q15.4 U5.15 | length 797
  Top Layer w13: v5@6282.2,8712.2 U5.15@6282.2,8762.8
  Top Layer w14: v5@6280,8710 v5@6282.2,8712.2
  Top Layer w16: Q15.4@6249.3,8020.49 6290.49,8020.49 v7(6300,8030)
  Signal Layer 3 w14: 6280,8675 6280,8678.37 6280.5,8678.87 6280.5,8709.5 v5@6280,8710
  Signal Layer 3 w16: 6280,8675 6280,8505 6300,8485 v7(6300,8030)
  other v5: 6280,8709
NetQ16_1: Q16.1 Q17.1 U11.4 | length 339.2
  Top Layer w10: v5(1785,8380) 1802.24,8397.24 Q17.1@1802.24,8427.6
  Bottom Layer w10: v5(1785,8380) 1870,8380 1885,8395 Q16.1@1885,8430
  Bottom Layer w12: Q16.1@1892.6,8427.6 U11.4@2035.87,8427.6
NetQ18_1: Q18.1 U12.4 | length 102.9
  Top Layer w12: v5@1820,9215 1837.76,9232.76 Q18.1@1877.6,9232.76
  Bottom Layer w10: v5@1820,9215 1820.87,9215.87 U12.4@1820.87,9252.6
  other v5: 1817.6,9215
NetQ19_1: Q19.1 R185.1 R190.2 | length 244.1
  Bottom Layer w24: R185.1@6190,1780 6275,1780 R190.2@6280,1785 ; Q19.1@6270,1935 6275,1930 6275,1855 R190.2@6275,1785
NetQ20_1: Q20.1 R188.1 R191.2 | length 269.3
  Bottom Layer w24: R188.1@6010,1475 R188.1@6020,1485 ; Q20.1@6015,1618.94 R188.1@6015,1490 R188.1@6020,1485 ; R188.1@6030,1475 R188.1@6020,1485 ; R191.2@6125,1485 R188.1@6020,1485
NetQ21_1: Q21.1 R189.1 R192.2 | length 256
  Bottom Layer w24: R189.1@5515,1480 R189.1@5515,1490 ; Q21.1@5515,1618.94 R189.1@5515,1490 ; R192.2@5630,1485 5625,1490 R189.1@5515,1490
NetQ22_1: Q22.1 R193.1 R194.2 | length 230
  Bottom Layer w24: R193.1@6195,2365 6285,2365 ; R194.2@6285,2295 6285,2365 ; Q22.1@6285,2435 6285,2365
NetR10_2: R10.2 U7.4 | length 83
  Top Layer w16: U7.4@5793.07,9082.6 5872.4,9082.6 R10.2@5875,9080
NetR11_2: R11.2 U1.48 | length 158
  Bottom Layer w8: U1.48@3208.27,6418.46 3208.27,6473.27 3218.33,6483.33 3252.44,6483.33 3252.44,6485 R11.2@3252.44,6538.21
NetR13_2: R13.2 U1.47 | length 130.8
  Bottom Layer w8: U1.47@3188.58,6418.46 3188.58,6483.58 3205,6500 R13.2@3205,6542.44
NetR15_2: R15.2 R102.1 U1.30 | length 1014
  Top Layer w9.8: v7(2950,6620) R102.1@3052.44,6620
  Signal Layer 2 w9.8: v7@2645,6315 v7(2650,6320) 2715,6385 ; 2715,6380 2715,6385 ; v7(2950,6620) 2770,6620 2715,6565 2715,6385
  Bottom Layer w8: v7(2650,6320) 2650,6293.89 2671.94,6271.94 2768.06,6271.94 2775,6265 R15.2@2775,6240 ; R15.2@2776.5,6240 R15.2@2776.5,6253.5 ; R15.2@2777.56,6240 2805,6240 2815.16,6250.16 U1.30@2941.54,6250.16
NetR16_3: R16.3 R31.2 | length 5978.7
  Top Layer w9.8: R31.2@2597.56,6680 2640,6680 2660,6660 v5(2660,6640) ; R16.3@4255,2180 4255,2160 4295,2120 v5(4305,2120)
  Signal Layer 4 w9.8: v5(2660,6640) 2667.33,6640 2682.33,6625 2682.33,6117.67 2882.67,5917.33 2990.01,5917.33 ; 2992.68,5917.33 2990.01,5917.33 ; 3145,5760 3147.85,5757.15 3150.18,5757.15 ; v5(4305,2120) 4327.33,2142.33 4327.33,5442.67 4012.85,5757.15 3150.18,5757.15 ; 2990.01,5917.33 3150.18,5757.15
NetR16_4: R16.4 R42.2 | length 6393.4
  Top Layer w9.8: R42.2@2595,6905 R42.2@2597.56,6905 2645,6905 v7(2660,6890)
  Top Layer w10: R16.4@4251.5,1997.36 4347.64,1997.36 v7(4370,1975)
  Signal Layer 4 w9.8: v7(2660,6890) 2720,6830 2720,6129.99 2897.32,5952.68 3007.33,5952.68 3167.5,5792.5 4032.5,5792.5 4370,5455 v7(4370,1975)
NetR21_3: R21.3 R56.2 | length 1953.9
  Top Layer w9.8: v5(2650,6420) R56.2@2706.38,6420 ; R21.3@3332.36,5031.3 3406.3,5031.3 3430,5055 v5(3430,5080)
  Signal Layer 4 w9.8: v5(2650,6420) 2635,6405 2595,6405 2565,6375 2565,6060 3415,5210 3415,5140.04 3405.23,5130.26 3405.23,5104.77 v5(3430,5080)
NetR21_4: R21.4 R57.2 | length 1905.9
  Top Layer w9.8: v5(2650,6370) R57.2@2706.38,6370 ; v5(3430,5120) 3455,5095 3455,5045 3468.5,5031.5 R21.4@3527.64,5031.5
  Signal Layer 4 w9.8: v5(2650,6370) v5@2650,6375 ; v5@2650,6378.27 v5@2650,6375 ; v5@3432.67,5122.67 3432.67,5217.32 2582.67,6067.32 2582.67,6367.68 2602.32,6387.33 2637.67,6387.33 v5@2650,6375
NetR32_3: R32.3 R59.2 | length 1942
  Top Layer w9.8: R59.2@3497.56,6340 3530,6340 v7(3535,6335) ; R32.3@4662.36,5041.3 4740.77,5041.3 4760,5060.53 v5(4760,5080) v5@4760,5085
  Signal Layer 4 w9.8: v7@3530,6340 v7(3535,6335) 3540,6335 4735.23,5139.77 4735.23,5109.74 4760,5084.96 v5(4760,5080)
NetR32_4: R32.4 R58.2 | length 1960.1
  Top Layer w9.8: R58.2@3500,6390 3525,6390 v5(3552.57,6362.43) ; v5(4760,5120) 4785,5095 4785,5055 4798.5,5041.5 R32.4@4857.64,5041.5
  Signal Layer 4 w9.8: v5(3552.57,6362.43) 3565,6350 3565,6335 4760,5140 v5(4760,5120)
NetR45_1: R45.1 U6.10 | length 102.2
  Bottom Layer w9.8: U6.10@5262.4,6191.1 5318.9,6191.1 5330,6180 R45.1@5358.5,6180 R45.1@5360,6180
NetR46_2: R46.2 U5.3 | length 165.4
  Top Layer w10: U5.3@6358.98,8987.2 6358.98,9083.98 6378.11,9103.11 R46.2@6378.11,9144.64
NetR50_2: R50.2 R51.1 | length 60
  Top Layer w10: R51.1@5997.44,8965 R50.2@5997.44,9025
NetR52_2: R52.2 U8.2 U8.6 VBAT.1 | length 475.9
  Top Layer w12: U8.2@1875,7940 U8.2@1875,7941.65 1875,8005 1925,8055 U8.6@1925,8148.35 1925,8195 ; R52.2@1923.5,8240 1923.5,8241.5 1925,8240 1925,8195 ; VBAT.1@2060,8155 2020,8195 1925,8195
NetR53_2: R53.2 U5.2 | length 233
  Top Layer w10: U5.2@6384.57,8987.2 6384.57,9059.57 6427.44,9102.44 6427.44,9160 R53.2@6427.44,9202.44
NetR60_1: R60.1 U1.10 | length 111.1
  Bottom Layer w8: U1.10@3258.46,6191.1 3328.9,6191.1 3340,6180 3362.44,6180 R60.1@3365,6180
NetR67_2: R67.2 U9.6 | length 168.9
  Top Layer w10: U9.6@3058.5,7576.5 3060,7575 3110,7575 3125,7560 3125,7466.5 R67.2@3126.5,7465
NetR68_2: R68.2 U9.1 U9.5 | length 698.9
  Top Layer w10: R68.2@2620,7645 R68.2@2620,7638.5 2620,7605 2630,7595 2775,7595 2853.43,7673.43 2869.06,7673.43 2900.2,7704.57 U9.1@3062.8,7704.57 3090.43,7704.57 3100,7695 3100,7610 3092.2,7602.2 U9.5@3062.8,7602.2
NetR69_2: R69.2 U9.2 U9.3 | length 448.8
  Top Layer w10: R69.2@2695,7640 v5(2745,7640) ; U9.3@3062.8,7653.39 3011.61,7653.39 v5(3010,7655) 3010,7670 3020,7680 U9.2@3065,7680
  Signal Layer 2 w10: v5(2745,7640) 2995,7640 v5(3010,7655)
NetR70_1: R70.1 R200.1 U13.8 | length 192.3
  Top Layer w12: R200.1@2495,7850 2496.5,7851.5 R70.1@2496.5,7910 ; R70.1@2495,7920 2495,7945 2547.28,7997.28 U13.8@2580,7997.28
NetR70_2: R70.2 S3.2 | length 254
  Top Layer w10: S3.2@2247.24,7795 v11@2295,7795 ; v11@2350,7900 2360,7910 R70.2@2433.5,7910
  Signal Layer 2 w10: v11@2295,7795 2340,7840 v11(2340,7895)
  other v11: 2305,7800
NetR71_2: R71.2 U13.6 | length 152.7
  Top Layer w12: U13.6@2680,7997.28 R71.2@2680,8150
NetR72_1: R72.1 U14.2 U14.6 | length 308.1
  Top Layer w12: U14.2@2630,8346.65 2630,8415 2680,8465 U14.6@2680,8550 ; U14.6@2680,8553.35 2680,8595 R72.1@2710,8625
NetR92_2: R92.2 R94.1 U6.33 | length 214.3
  Bottom Layer w9.8: R92.2@4735.07,6303.5 4796.5,6303.5 R94.1@4800,6300 ; R94.1@4790,6310 4790.79,6309.21 U6.33@4937.6,6309.21
NetR94_2: R94.2 U6.34 | length 152.6
  Bottom Layer w9.8: R94.2@4800,6365 4836.1,6328.9 U6.34@4937.6,6328.9
NetR96_1: R96.1 U16.6 | length 200.5
  Top Layer w10: v5(2875,9385) U16.6@2952.72,9385
  Bottom Layer w10: v5(2875,9385) 2920,9385 R96.1@2975,9330
NetR111_2: R111.2 R113.2 R119.1 | length 404.6
  Top Layer w8: R111.2@4265,8830 R111.2@4266.5,8830 4266.5,8786.5 4237.87,8757.87 4230.53,8757.87 4217.13,8744.47 4217.13,8657.87 4260,8615 4320,8615 R119.1@4325,8610
  Top Layer w12: R111.2@4265,8830 R113.2@4265,8903.5 ; R119.1@4325,8610 R119.1@4330,8610
NetR115_2: R115.2 R117.2 R118.1 | length 963.5
  Top Layer w12: v7(3550,8690) 3550,8700 3560,8710 3595,8745 R117.2@3663.5,8745 ; v7(4255,8665) 4303.5,8665 4308.5,8660 R118.1@4323.5,8675
  Signal Layer 5 w12: v7(3550,8690) 3555,8690 3560,8685 3605,8640 4159.82,8640 4164.95,8634.87 4169.7,8630.13 4175.05,8630.13 4175.42,8629.75 4182.13,8629.75 4196.03,8629.75 4197.03,8630.75 4200.93,8630.75 4210.18,8640 4230,8640 4250,8660 v7(4255,8665)
NetR116_1: R116.1 U19.7 | length 89.7
  Top Layer w12: R116.1@3721.5,8880 3752.02,8880 3766.95,8865.06 3804.94,8865.06 U19.7@3805,8865
NetR120_1: R120.1 U21.30 | length 89.7
  Top Layer w10: R120.1@4630,8715 4635,8715 4675.47,8674.53 U21.30@4675.47,8647.05
NetR124_2: R124.2 R127.1 R128.2 | length 524.2
  Top Layer w12: R124.2@4260,8200 4270,8210 R128.2@4270,8268.5 ; R124.2@4261.5,8200 4261.5,8153.5 v7(4270,8145) ; v5(4265,8465) R127.1@4323.5,8465
  Signal Layer 3 w12: v5(4265,8465) 4250,8450 4250,8165 v7(4270,8145)
NetR125_1: R125.1 R130.2 R132.2 | length 1210.3
  Top Layer w12: v7@3496.5,8133.5 R130.2@3600,8133.5 ; R130.2@3600,8130 3605,8135 R132.2@3673.5,8135 ; v7(4265,8515) 4300,8515 R125.1@4320,8535 ; R125.1@4321.75,8533.25 R125.1@4323.5,8535
  Signal Layer 2 w12: v7(3495,8135) 3595,8235 4015,8235 4075,8295 4100,8295 4170,8365 4170,8430 4255,8515 v7(4265,8515)
NetR131_1: R131.1 U20.7 | length 86.8
  Top Layer w12: R131.1@3735,8265 3757.8,8242.2 U20.7@3812.4,8242.2
NetR135_1: R135.1 R137.2 U21.25 | length 301.1
  Top Layer w10: U21.25@4773.9,8647.05 4837.05,8647.05 4890,8700 4890,8730 R137.2@4885,8735 ; R137.2@4886.5,8735 4925,8773.5 R135.1@4925,8845
NetR136_2: R136.2 R137.1 U21.26 | length 273.5
  Top Layer w10: U21.26@4754.21,8647.05 4754.21,8671.64 4767.58,8685 4810,8685 4825,8700 R137.1@4825,8735 ; R136.2@4795,8845 4835,8805 4835,8746.5 R137.1@4823.5,8735
NetR140_1: R140.1 U23.64 | length 172.5
  Top Layer w8: v3(3530,8525) 3530,8555 3541.5,8566.5 R140.1@3585,8566.5
  Bottom Layer w6: 3540,8560 3544.09,8564.09 U23.64@3581.85,8564.09
  Bottom Layer w8: v3(3530,8525) 3530,8550 3540,8560
NetR142_2: R142.2 U23.9 | length 196.3
  Top Layer w8: R142.2@3983.5,7945 3983.5,8068.5 v3(3990,8075)
  Bottom Layer w6: v3(3990,8075) 4003.11,8061.89 U23.9@4003.11,8016.85
NetR143_1: R143.1 U23.59 | length 108.8
  Bottom Layer w6: 3535,8490 3539.65,8485.35 U23.59@3581.85,8485.35
  Bottom Layer w8: R143.1@3475,8490 R143.1@3476.5,8490 3535,8490
NetR144_1: R144.1 R167.2 U6.30 | length 984.7
  Top Layer w12: v5(4950,6620) R144.1@5052.44,6620 R144.1@5055,6620
  Signal Layer 2 w9.8: v5(4660,6320) 4715,6375 4715,6565 4770,6620 v5(4950,6620)
  Bottom Layer w8: 4660,6298.33 4660,6300 ; v5(4660,6320) 4660,6300 ; 4700,6270.57 4689.43,6270.57 ; R167.2@4776.5,6240 4776.5,6263.5 4769.43,6270.57 4689.43,6270.57 ; 4660,6300 4689.43,6270.57
  Bottom Layer w9.8: R167.2@4775,6240 R167.2@4776.5,6240 4820,6240 4830.16,6250.16 U6.30@4937.6,6250.16
NetR145_2: R145.2 U23.89 | length 350.9
  Signal Layer 3 w8: v3(4019,8681) 4019,8719 4160,8860 v3(4165,8860)
  Bottom Layer w6: U23.89@4018.86,8623.15 4018.86,8678.86 v3@4020,8680
  Bottom Layer w8: v3(4165,8860) 4180,8875 R145.2@4180,8905
NetR148_2: R148.2 U6.48 | length 137
  Bottom Layer w10: U6.48@5208.27,6422.4 5208.27,6453.27 5255,6500 R148.2@5255,6540
NetR149_1: R149.1 U27.22 | length 108.5
  Bottom Layer w10: U27.22@4410,8910 4410,8985 4418.5,8993.5 R149.1@4440,8993.5
NetR153_2: R153.2 U27.24 | length 122.2
  Bottom Layer w10: U27.24@4448.9,8913.31 4478.31,8913.31 4505,8940 R153.2@4505,8993.5 R153.2@4505,8995
NetR155_1: R155.1 R156.2 U1.33 | length 205
  Bottom Layer w8: R156.2@2735,6303.5 2798.5,6303.5 2800,6305 2885,6305 2889.21,6309.21 U1.33@2937.6,6309.21
NetR155_2: R155.2 U1.34 | length 154.6
  Bottom Layer w8: R155.2@2800,6370 2841.1,6328.9 U1.34@2937.6,6328.9
NetR158_2: R158.2 U6.47 | length 129.4
  Bottom Layer w10: U6.47@5188.58,6422.4 5188.58,6458.86 5205,6475.28 R158.2@5205,6542.44 R158.2@5205,6545
NetR173_3: R173.3 R177.2 | length 7205.4
  Top Layer w9.8: v5(4660,6420) 4700,6420 R177.2@4710,6430
  Signal Layer 4 w9.8: 4255,1600 4257.67,1597.33 4257.67,1502.33 4350,1410 4500,1410 4590,1500 4590,2770 4515,2845 4515,4740 4825,5050 4825,5460 4405,5880 4405,6175 4630.95,6400.95 4650,6400.95 v5@4660,6410.95
  Signal Layer 4 w10: v5@3430.14,2425 4257.57,1597.57
  Bottom Layer w10: R173.3@3340,2460 3410,2460 3430,2440 v5(3430,2425)
NetR173_4: R173.4 R178.2 | length 7259.7
  Top Layer w9.8: v15(4660,6370) 4705,6370 R178.2@4710,6375
  Signal Layer 4 w9.8: 4240,1565 4240,1490 4337.67,1392.33 4512.33,1392.33 4607.67,1487.67 4607.67,2777.32 4532.67,2852.32 ; 4545,2840 4532.67,2852.33 4532.67,4732.68 4842.67,5042.68 4842.67,5467.32 4422.67,5887.32 4422.67,6167.68 4638.27,6383.28 4645,6383.28 ; 4646.72,6383.28 v15(4660,6370)
  Signal Layer 4 w10: v5(3430,2385) 3444.86,2385 4239.9,1589.96 4239.9,1560
  Bottom Layer w9.8: v5(3430,2385) 3460,2415 3460,2455 3465,2460 R173.4@3530,2460
NetR184_3: R184.3 R187.2 | length 4647.2
  Top Layer w9: R187.2@5497.56,6340 5530,6340 v3(5535,6335)
  Signal Layer 4 w9.8: 4742.33,4842.33 4955,5055 4955,5420 5655,6120 5655,6215 v3(5535,6335)
  Signal Layer 4 w10: 4752.43,4852.57 4687.13,4787.27 4687.13,2457.87 v5(4760,2385)
  Bottom Layer w10: R184.3@4660,2465 4730,2465 4735,2460 4735,2410 v5(4760,2385)
NetR184_4: R184.4 R186.2 | length 7038
  Top Layer w9: R186.2@5497.56,6390 5525,6390 v3(5550,6365)
  Signal Layer 4 w9.8: 4760,4835.01 4972.67,5047.68 4972.67,5412.68 5672.67,6112.68 ; v3@5552.57,6362.43 5565,6350 5565,6335 5672.67,6227.33 5672.67,6112.68 ; 5637.5,6067.5 5672.67,6102.68 5672.67,6112.68 ; 5672.67,6140 5672.67,6112.68
  Signal Layer 4 w10: 4720.07,4794.93 4705.07,4779.93 ; v5(4760,2425) 4745.28,2425 4705,2465.28 4705,2480 ; 4770.07,4844.93 4705.07,4779.93 ; 4705,2480 4705.07,2479.93 4705.07,4779.93 ; 4705,2480 4705,4779.86 4705.07,4779.93
  Bottom Layer w10: v5(4760,2425) 4760,2445 4780,2465 R184.4@4865,2465
NetR200_2: R200.2 S3.3 | length 189.7
  Top Layer w10: S3.3@2250,7830 2265,7845 R200.2@2433.5,7845
NetS3_1: S3.1 U13.1 | length 362
  Top Layer w10: S3.1@2250,7760 2265,7745 2335,7745 2385,7795 2567.72,7795 U13.1@2580,7782.72
NetU10_4: U10.4 U12.2 | length 156.9
  Bottom Layer w12: U12.2@1929.13,9290 1965,9290 1977.4,9277.6 U10.4@2080.87,9277.6
NFAULT: J2.3 U1.27 | length 2385.2
  Signal Layer 3 w9.8: v5@2870,6180 2865,6180 2815,6230 2815,6920 2925,7030 3410,7030 3482.5,7102.5 3482.5,7247.5 ; 3480,7245 3482.5,7247.5 ; J2.3@3905,7720 3900,7715 3900,7665 3482.5,7247.5
  Bottom Layer w9.8: v5(2865.55,6180.55) 2876.1,6191.1 U1.27@2937.6,6191.1 U1.27@2941.54,6191.1
nFAULT2: J28.3 U6.27 | length 1983.5
  Signal Layer 2 w9.8: v5(4865.55,6180.55) 4825,6140 ; 4825,6140 v5(4470,6140) 4825,6140
  Signal Layer 3 w9.8: v5(4470,6140) 4470,6615 4890,7035 J28.3@4890,7105
  Bottom Layer w9.8: v5@4865,6180 v5(4865.55,6180.55) 4876.1,6191.1 U6.27@4937.6,6191.1
OPT: J2.1 J5.2 U1.29 | length 2511.8
  Signal Layer 3 w8: J5.2@3295,7100 3295,7530 3505,7740 3780,7740 J2.1@3800,7720
  Signal Layer 3 w10: v5(2805,6201) 2805,6214.86 2797.23,6222.64 2797.23,6952.23 2892.77,7047.77 3242.77,7047.77 J5.2@3295,7100 ; J2.1@3800,7720 J2.1@3800,7740
  Bottom Layer w8: v5(2805,6201) 2821,6201 2850,6230 ; 2850.47,6230.47 U1.29@2937.6,6230.47 U1.29@2941.54,6230.47
OPT2: J28.1 J29.2 U6.29 | length 1912.3
  Signal Layer 2 w9.8: v5(4285,6290) 4395,6180 4785,6180 v5@4805,6200
  Signal Layer 3 w8: J29.2@4285,6735 4285,6885 4510,7110 J28.1@4790,7110
  Signal Layer 3 w9.8: v5(4285,6290) J29.2@4285,6735
  Bottom Layer w9.8: v5@4805,6200 4835.47,6230.47 U6.29@4937.6,6230.47
  other v5: 4805,6201
OVPA: C82.1 J2.19 R17.2 U1.9 | length 2697.1
  Signal Layer 2 w10: v5@3390,6230 3400,6240 v5(3740,6240)
  Signal Layer 3 w10: v5(3740,6240) 3740,6445.28 4545,7250.28 4545,7765 4570,7790 4645,7790 J2.19@4700,7735 ; J2.19@4700,7720 J2.19@4720,7720
  Bottom Layer w8: U1.9@3258.46,6210.79 3370.79,6210.79 v5(3385,6225) 3394.49,6234.49 3477.44,6234.49 R17.2@3479.49,6234.49
  Bottom Layer w10: R17.2@3477.44,6234.49 C82.1@3477.44,6280
OVPA2: C202.1 J28.19 R169.2 U6.9 | length 1527.5
  Signal Layer 2 w10: v5(5385,6225) 5400,6240 v3(5740,6240)
  Signal Layer 3 w10: J28.19@5690,7110 5740,7060 v3(5740,6240)
  Bottom Layer w9.8: U6.9@5262.4,6210.79 5300.79,6210.79 5310,6220 5385,6220 v5(5385,6225) 5390,6230 5475,6230 5475,6275 C202.1@5480,6280
OVPB: C83.1 J2.17 R18.2 U1.25 | length 3181.4
  Signal Layer 2 w10: v5(2865,6075) 2865,6115 2900,6150 v5(3595,6150)
  Signal Layer 3 w10: v5(3595,6150) 3750,6150 3795,6195 3795,6310.51 3794.65,6310.86 3794.65,6474.65 4600,7280 J2.17@4600,7740
  Bottom Layer w8: R18.2@2777.56,6015 2810,6015 2865,6070 v5(2865,6075) 2865,6115 2901.73,6151.73 U1.25@2941.54,6151.73
  Bottom Layer w10: C83.1@2767.56,5960 R18.2@2767.56,6012.56
OVPB2: C203.1 J28.17 R170.2 U6.25 | length 2731.3
  Signal Layer 2 w10: v5(4865,6075) 4865,6115 4900,6150 ; 4900,6150 v3(5590,6150) 4900,6150
  Signal Layer 3 w10: v3(5590,6150) J28.17@5590,7110
  Bottom Layer w10: C203.1@4770,5955 4770,6015 4805,6015 v5(4865,6075)
  Bottom Layer w11: 4911.73,6151.73 U6.25@4937.6,6151.73
  Bottom Layer w12: v5(4865,6075) 4865,6105 4911.73,6151.73
PGND: C10.2 C18.2 C20.2 C21.2 C22.2 C23.2 C24.2 C25.2 C26.2 C27.2 C28.2 C29.2 C32.2 C38.2 C39.2 C40.2 C42.2 C43.2 C47.2 C48.2 C50.2 C51.2 C52.2 C53.2 C54.2 C55.2 C56.2 C57.2 C58.2 C59.2 C60.2 C61.2 C62.2 C63.2 C64.2 C65.2 C66.2 C67.2 C68.2 C69.2 C70.2 C71.2 C193.2 C206.2 C207.2 C208.2 C209.2 C210.2 C211.2 C212.2 C213.2 C214.2 C215.2 C216.2 C217.2 J11.1 J12.1 NT1.2 NT2.2 NT3.2 Q2.3 Q3.3 Q6.3 Q8.3 Q11.3 Q12.3 Q15.1 Q15.2 Q15.3 Q20.3 Q21.3 R24.2 R25.2 R35.2 R36.2 R47.1 R175.2 R176.2 R188.2 R189.2 T3.1 T4.1 U1.18 U5.13 U5.14 U5.21 U6.18 | length 27640.6
  Top Layer w10: v5@6215,8685 6215,8695 6231.02,8711.02 U5.13@6231.02,8762.8 U5.13@6230,8790
  Top Layer w13: C48.2@6257.44,8650 6253.63,8653.82 v5(6253.63,8690) 6253.63,8723.63 6256.61,8726.61 U5.14@6256.61,8762.8 6256.61,8836.61 U5.21@6295,8875
  Signal Layer 2 w10: v5(6210,8685) 6195,8670 6195,8595.28 6265,8525.28 6265,7975.28 6285.28,7955 6590,7955 6610.13,7975.13 6610.13,7975.3 6624.7,7989.87 6645.3,7989.87 6659.87,7975.3 6659.87,7975.13 6660,7975 6660,7960 6659.87,7959.87 6659.87,7949.87 6635,7925 v7(6635,7920)
  Signal Layer 2 w24: v1(2850,3975) 3070.08,3975 3361.87,4266.8 3361.87,5243.13 3116.87,5488.13 3116.87,5860 ; v1(3078.24,1715) 3078.24,1763.24 3361.87,2046.87 3361.87,2801.8 3880.08,3320 4700,3320 4873.13,3493.13 6878.2,3493.13 6981.87,3596.8 6981.87,5393.2 6645.08,5730 5070,5730 5010,5790 5010,5835 5076.46,5901.46 5110,5901.46 ; v5(3110,6015) 3110,5901.46 3116.87,5894.58 3116.87,5860 ; v5(5110,6015) 5110,5901.46 ; v1(5600,3975) 5004.92,3975 4830,4149.92 4830,5120 4496.87,5453.13 4496.8,5453.13 4091.8,5858.13 3118.75,5858.13 3116.87,5860 ; v1(5765,1590) 5425,1590 5260,1755 5059.92,1755 4803.13,2011.8 4803.13,3123.2 4830,3150.08 4830,3155 5105,3430 6940,3430 7065,3555 7065,5579.92 6809.92,5835 5176.46,5835 5110,5901.46
  Signal Layer 3 w13: v5(6253.63,8690) 6253.63,8499 6277.63,8475 6277.63,8044.92 6273.63,8040.92 6273.63,8015.08 6277.63,8011.08 6277.63,8002.37 v7(6300,7980)
  Bottom Layer w9.8: U6.18@5109.84,6097.6 5109.84,6015.16 v5(5110,6015)
  Bottom Layer w10: 3109.84,6029.63 3109.84,6029.84 U1.18@3109.84,6101.54
  Bottom Layer w12: 3095.35,6015.35 3109.84,6029.84 3110,6030
  Bottom Layer w13: C47.2@6335,8802.56 6335,8855.94 v6(6354.06,8875)
  Bottom Layer w20: v5(5110,6015) 5130,5995 C193.2@5130,5920
  Bottom Layer w24: Q21.3@5315,1615 5315,1520 5345,1490 R189.2@5435,1490 ; Q20.3@5820,1630 5820,1520 5850,1490 R188.2@5935,1490
  other v1: 3795,95 3865,95 3935,95 4030,95 4100,95 4170,95 4265,95 4335,95 4405,95 6340,650 6410,650 6480,650 6570,650 6640,650 6710,650 6800,650 6870,650 6940,650 7010,650 7080,650 7150,650 7245,650 7315,650 7385,650 7465,650 7535,650 7605,650 7680,650 7750,650 7820,650 7915,650 7985,650 8055,650 8135,650 8205,650 75,675 155,675 225,675 295,675 390,675 460,675 530,675 605,675 675,675 745,675 825,675 895,675 965,675 1060,675 1130,675 1200,675 1265,675 1335,675 1405,675 1485,675 1555,675 1625,675 1720,675 1790,675 1860,675 2040,1365 2110,1365 2180,1365 2250,1365 2320,1365 2390,1365 2460,1365 2600,1365 2670,1365 2740,1365 2810,1365 2880,1365 2950,1365 3020,1365 3090,1365 3150,1365 5095,1365 5165,1365 5235,1365 5305,1365 5375,1365 5445,1365 5515,1365 5585,1365 5655,1365 5725,1365 5795,1365 5865,1365 5935,1365 6005,1365 6075,1365 2040,1435 2110,1435 2180,1435 2250,1435 2320,1435 2460,1435 2530,1435 2600,1435 2670,1435 2740,1435 3090,1435 3150,1435 5095,1435 5165,1435 5235,1435 5305,1435 5375,1435 5725,1435 2040,1505 2110,1505 3078.24,1505 3148.24,1505 5095,1505 5165,1505 5235,1505 2040,1575 2110,1575 3078.24,1575 3148.24,1575 5095,1575 5165,1575 5235,1575 2610,1585 2040,1645 2110,1645 3078.24,1645 3148.24,1645 5095,1645 5165,1645 5235,1645 2040,1715 2110,1715 3148.24,1715 5095,1715 5165,1715 5235,1715 5585,1715 2405,1730 1265,2840 1335,2840 1405,2840 1485,2840 1555,2840 1625,2840 1790,2840 1880,3080 7120,3475 2165,3705 2250,3705 2185,3740 2015,3780 2320,3780 2390,3780 2600,3780 2670,3780 2740,3780 2810,3780 5095,3780 5165,3780 5235,3780 5305,3780 5375,3780 5445,3780 5515,3780 5585,3780 5655,3780 5725,3780 5795,3780 5865,3780 5935,3780 6005,3780 6075,3780 2015,3850 5515,3850 5585,3850 6005,3850 6075,3850 6145,3850 2015,3920 5585,3920 6075,3920 6145,3920 2015,3990 6075,3990 6145,3990 2040,4060 6075,4060 6145,4060 2480,4065 5235,4130 5585,4130 5655,4130 6075,4130 6145,4130 2480,4135 2550,4135 2405,4145 6170,5325 6320,5325 6170,5395 6320,5395 6320,5465 7155,5840 7155,5890 6580,6075 6650,6075 6720,6075 6780,6075 1200,7020 1300,7020 6520,7555 6340,7625 6520,7625 6340,7695 6520,7695 6340,7765 6520,7765 6340,7835 6520,7835
  other v4: 2875,80 2915,80 2955,80 2995,80 3035,80 3075,80 3125,80 3165,80 3205,80 3245,80 3285,80 3325,80 5650,80 5690,80 5730,80 5770,80 5810,80 5850,80 5900,80 5940,80 5980,80 6020,80 6060,80 6100,80 2875,120 2915,120 2955,120 2995,120 3035,120 3075,120 3125,120 3165,120 3205,120 3245,120 3285,120 3325,120 5650,120 5690,120 5730,120 5770,120 5810,120 5850,120 5900,120 5940,120 5980,120 6020,120 6060,120 6100,120 2875,160 2915,160 2955,160 2995,160 3035,160 3075,160 3125,160 3165,160 3205,160 3245,160 3285,160 3325,160 5650,160 5690,160 5730,160 5770,160 5810,160 5850,160 5900,160 5940,160 5980,160 6020,160 6060,160 6100,160 2875,200 2915,200 2955,200 2995,200 3035,200 3075,200 3125,200 3165,200 3205,200 3245,200 3285,200 3325,200 5650,200 5690,200 5730,200 5770,200 5810,200 5850,200 5900,200 5940,200 5980,200 6020,200 6060,200 6100,200 2875,686.27 3325,686.27 5650,686.27 6100,686.27 2875,726.27 3325,726.27 5650,726.27 6100,726.27 2875,766.27 2915,766.27 2955,766.27 3245,766.27 3285,766.27 3325,766.27 5650,766.27 5690,766.27 5730,766.27 6020,766.27 6060,766.27 6100,766.27 6340,7555
  other v5: 2550,6025
  other v6: 6235.94,8835.63 6275.32,8835.63 6314.69,8835.63 6354.06,8835.63 6235.94,8875 6275.32,8875 6314.69,8875 6235.94,8914.37 6275.32,8914.37 6314.69,8914.37 6354.06,8914.37
SCLK: J17.8 U17.14 | length 624.3
  Top Layer w8: U17.14@3174.06,8930.87 3200.87,8930.87 3360,9090 3535,9090 v7(3565,9120)
  Bottom Layer w8: v7(3565,9120) J17.8@3565,9275
SDIN: J17.4 U17.13 | length 889.3
  Top Layer w8: U17.13@3154.37,8930.87 3155,8930.24 3155,8900 3160,8895 3195,8895 3360,9060 3705,9060 3760,9115 v7@3760,9120
  Bottom Layer w8: v7(3765,9120) J17.4@3765,9275
SDO: J17.3 U17.8 | length 1296.1
  Top Layer w8: U17.8@3055.94,8930.87 3035,8909.92 3034.92,8909.92 3000,8875 3000,8815 3020,8795 3125,8795 3175,8845 3220,8845 3380,9005 v7(3635,9005)
  Bottom Layer w8: v7(3635,9005) 3715,9085 3715,9330 3760,9375 J17.3@3765,9375
SPI_CS: J19.6 U23.36 | length 2436.1
  Signal Layer 3 w8: v3(3440,8105) 3440,8110 3415,8135 3415,8185 3470,8240 3470,8655 3483.62,8668.62 3510.86,8695.86 3524.47,8709.47 3524.47,8719.47 4189.6,9384.6 4237.15,9384.6 4238.42,9385.87 4625.58,9385.87 4627.85,9383.6 4662.15,9383.6 4664.42,9385.87 4725.58,9385.87 4727.85,9383.6 4762.15,9383.6 4764.42,9385.87 4805.87,9385.87 J19.6@4845,9425
  Bottom Layer w6: v3(3440,8105) 3510,8105 3528.15,8123.15 U23.36@3581.85,8123.15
